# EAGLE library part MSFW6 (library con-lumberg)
MSF CONNECTOR
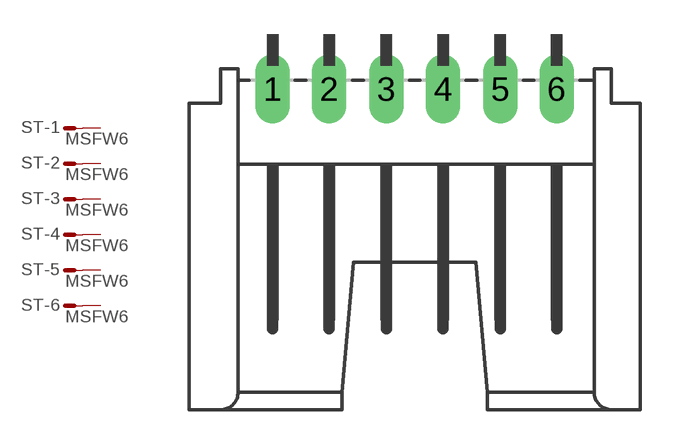
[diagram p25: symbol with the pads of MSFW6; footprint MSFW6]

Designator prefix ST; gates -1=M -2=M -3=M -4=M -5=M -6=M

## MSFW6 (OC_FARNELL: unknown; OC_NEWARK: unknown)  [MSFW6]
1  -1:S  pas
2  -2:S  pas
3  -3:S  pas
4  -4:S  pas
5  -5:S  pas
6  -6:S  pas

## Footprint MSFW6 (pad centres in mm)
MSF CONNECTOR Buerklin Nr. 56 F 582
drill 1.016 long: 1 0,1.905; 2 2.489,1.905; 3 5.004,1.905; 4 7.493,1.905; 5 10.008,1.905; 6 12.497,1.905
